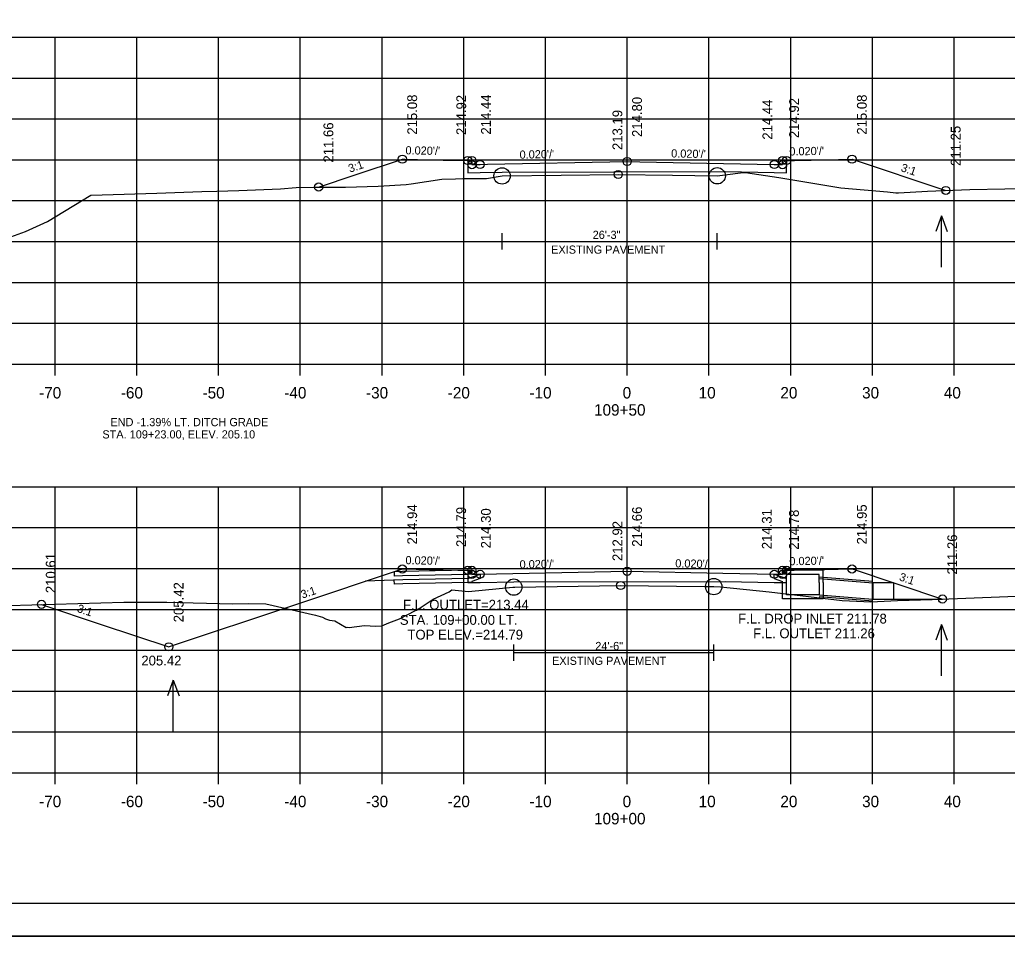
# Model space of a CAD drawing. Extents: x 1368968 to 1369915, y 377395 to 380381.
# Drawn here: x 1369063.8 to 1369184.6, y 379541.1 to 379653.2 of the extents above; entities that cross this region are included whole.
import ezdxf

# ---------------------------------------------------------------- set-up
doc = ezdxf.new("R2010")
doc.units = 0
for name, color, linetype in [('Default', 7, 'Continuous'), ('S_BORDER_NO_PLOT', 7, 'Continuous'), ('S_BREAKLINE_ANNOT', 7, 'Continuous'), ('S_BRIDGE', 7, 'Continuous'), ('S_BRIDGE_ANNOT', 7, 'Continuous'), ('S_CONTOUR_MAJOR', 7, 'Continuous'), ('S_CROSS_DRAIN', 7, 'Continuous'), ('S_CTL_TABLE', 7, 'Continuous'), ('S_CURB_ANNOT', 7, 'Continuous'), ('S_DITCHLINE_ANNOT', 7, 'Continuous'), ('S_DROP_INLET', 7, 'Continuous'), ('S_EXIST_ROW_ANNOT', 7, 'Continuous'), ('S_EXISTING_ALIGNMENT', 7, 'Continuous'), ('S_EXISTING_ALIGNMENT_ANNOT', 7, 'Continuous'), ('S_FENCE', 7, 'Continuous')]:
    doc.layers.add(name, color=color, linetype=linetype)

msp = doc.modelspace()

# ---------------------------------------------------------------- linework, layer by layer
at = {"layer": 'Default'}
for p, q in [((1369168.2, 379584.32), (1369168.2, 379582.32)), ((1369170.7, 379584.32), (1369168.2, 379584.32)), ((1369170.7, 379584.32), (1369170.7, 379582.32)), ((1369168.2, 379582.32), (1369176.7, 379582.32))]:
    msp.add_line(p, q, dxfattribs=at)
at = {"layer": 'S_BORDER_NO_PLOT'}
for points in [[(1369118.62, 379635.97), (1369118.63, 379634.46), (1369120.13, 379634.49), (1369122.82, 379634.54), (1369150.13, 379634.61), (1369156.13, 379634.49), (1369157.63, 379634.46), (1369157.64, 379635.97)], [(1369118.62, 379585.84), (1369118.63, 379584.33), (1369120.13, 379584.36), (1369124.25, 379584.44), (1369150.13, 379584.48), (1369156.13, 379584.36), (1369157.63, 379584.33), (1369157.64, 379585.84)]]:
    msp.add_lwpolyline(points, dxfattribs=at)
at = {"layer": 'S_BREAKLINE_ANNOT'}
for p, q in [((1368998.13, 379611.06), (1369278.13, 379611.06)), ((1369068.13, 379609.66), (1369068.13, 379611.06)), ((1369078.13, 379609.66), (1369078.13, 379611.06)), ((1369088.13, 379609.66), (1369088.13, 379611.06)), ((1369098.13, 379609.66), (1369098.13, 379611.06)), ((1369108.13, 379609.66), (1369108.13, 379611.06)), ((1369118.13, 379609.66), (1369118.13, 379611.06)), ((1369128.13, 379609.66), (1369128.13, 379611.06)), ((1369138.13, 379609.66), (1369138.13, 379611.06)), ((1369148.13, 379609.66), (1369148.13, 379611.06)), ((1369158.13, 379609.66), (1369158.13, 379611.06)), ((1369168.13, 379609.66), (1369168.13, 379611.06)), ((1369178.13, 379609.66), (1369178.13, 379611.06)), ((1368998.13, 379561.06), (1369278.13, 379561.06)), ((1369068.13, 379559.66), (1369068.13, 379561.06)), ((1369078.13, 379559.66), (1369078.13, 379561.06)), ((1369088.13, 379559.66), (1369088.13, 379561.06)), ((1369098.13, 379559.66), (1369098.13, 379561.06)), ((1369108.13, 379559.66), (1369108.13, 379561.06)), ((1369118.13, 379559.66), (1369118.13, 379561.06)), ((1369128.13, 379559.66), (1369128.13, 379561.06)), ((1369138.13, 379559.66), (1369138.13, 379561.06)), ((1369148.13, 379559.66), (1369148.13, 379561.06)), ((1369158.13, 379559.66), (1369158.13, 379561.06)), ((1369168.13, 379559.66), (1369168.13, 379561.06)), ((1369178.13, 379559.66), (1369178.13, 379561.06))]:
    msp.add_line(p, q, dxfattribs=at)
at = {"layer": 'S_BRIDGE_ANNOT'}
msp.add_line((1369296.31, 379545.06), (1368980.13, 379545.06), dxfattribs=at)
at = {"layer": 'S_CROSS_DRAIN'}
for p, q in [((1369122.82, 379626.08), (1369149.14, 379626.08)), ((1369124.25, 379575.78), (1369148.72, 379575.78))]:
    msp.add_line(p, q, dxfattribs=at)
at = {"layer": 'S_CTL_TABLE'}
for points in [[(1369062.7, 379626.63), (1369064.5, 379627.28), (1369067.18, 379628.52), (1369072.51, 379631.73), (1369073.87, 379631.79), (1369080.58, 379631.97), (1369086.1, 379632.18), (1369087.91, 379632.24), (1369090.59, 379632.31), (1369091.63, 379632.34), (1369095.7, 379632.52), (1369097.63, 379632.65), (1369099.93, 379632.72), (1369103.68, 379632.72), (1369107.67, 379632.83), (1369111.07, 379633.04), (1369111.69, 379633.13), (1369115.45, 379633.7), (1369117.11, 379633.72), (1369118, 379633.78), (1369118.81, 379633.77), (1369120.9, 379633.79), (1369122.82, 379634.08), (1369130.06, 379634.18), (1369137.03, 379634.26), (1369143.67, 379634.18), (1369149.14, 379634.1), (1369151.99, 379634.46), (1369152.6, 379634.51), (1369156.67, 379633.88), (1369164.27, 379632.61), (1369169.99, 379632.13), (1369171, 379632.03), (1369171.15, 379632.02), (1369171.32, 379632.02), (1369174.89, 379632.23), (1369180.04, 379632.41), (1369188.63, 379632.57)], [(1369062.46, 379581.55), (1369076.55, 379581.96), (1369081.81, 379581.95), (1369089.87, 379581.74), (1369091.78, 379581.78), (1369093.93, 379581.72), (1369100, 379580.37), (1369100.83, 379580.1), (1369101.21, 379579.91), (1369101.7, 379579.73), (1369102.35, 379579.67), (1369103.73, 379578.86), (1369103.88, 379578.87), (1369104.12, 379578.86), (1369106, 379579.1), (1369107.38, 379578.99), (1369108.11, 379579.04), (1369108.95, 379579.41), (1369110.26, 379579.89), (1369112.21, 379580.91), (1369112.36, 379580.97), (1369112.67, 379581.15), (1369114.38, 379582.32), (1369116.34, 379583.21), (1369116.69, 379583.47), (1369118.71, 379583.25), (1369124.15, 379583.76), (1369124.25, 379583.78), (1369124.39, 379583.78), (1369137.32, 379583.98), (1369147.57, 379583.87), (1369148.72, 379583.85), (1369149.55, 379583.82), (1369155.5, 379583.22), (1369164.44, 379582.13), (1369167.07, 379582.02), (1369167.95, 379581.99), (1369171.19, 379582.13), (1369175.45, 379582.27), (1369188.81, 379582.79)]]:
    msp.add_lwpolyline(points, dxfattribs=at)
at = {"layer": 'S_CURB_ANNOT'}
for points in [[(1369100.37, 379632.72), (1369104.86, 379634.21), (1369110.62, 379636.13), (1369110.94, 379636.13), (1369115.62, 379636.03), (1369115.72, 379636.03), (1369117.46, 379636), (1369118.62, 379635.97), (1369119.12, 379635.97), (1369119.13, 379635.47), (1369119.72, 379635.48), (1369120.13, 379635.49), (1369121.03, 379635.51), (1369138.13, 379635.85), (1369139.67, 379635.82), (1369149.93, 379635.62), (1369156.13, 379635.49), (1369156.59, 379635.48), (1369157.13, 379635.47), (1369157.14, 379635.97), (1369157.63, 379635.97), (1369157.64, 379635.97), (1369157.7, 379635.97), (1369158.6, 379635.99), (1369160.64, 379636.03), (1369165.64, 379636.13), (1369177.12, 379632.31)], [(1369066.47, 379581.67), (1369073.77, 379579.23), (1369082.04, 379576.48), (1369082.12, 379576.5), (1369097.32, 379581.57), (1369110.62, 379586), (1369115.62, 379585.9), (1369117.41, 379585.87), (1369118.62, 379585.84), (1369118.62, 379585.84), (1369119.12, 379585.84), (1369119.13, 379585.34), (1369119.73, 379585.35), (1369120.13, 379585.36), (1369138.13, 379585.72), (1369149.81, 379585.49), (1369156.1, 379585.36), (1369156.13, 379585.36), (1369156.59, 379585.35), (1369157.13, 379585.34), (1369157.14, 379585.84), (1369157.64, 379585.84), (1369158.55, 379585.86), (1369160.64, 379585.9), (1369160.64, 379585.9), (1369165.63, 379586), (1369165.64, 379586), (1369176.69, 379582.32), (1369176.7, 379582.32)]]:
    msp.add_lwpolyline(points, dxfattribs=at)
at = {"layer": 'S_DITCHLINE_ANNOT'}
for p, q in [((1368998.13, 379651.06), (1369278.13, 379651.06)), ((1369068.13, 379611.06), (1369068.13, 379651.06)), ((1369078.13, 379611.06), (1369078.13, 379651.06)), ((1369088.13, 379611.06), (1369088.13, 379651.06)), ((1369098.13, 379611.06), (1369098.13, 379651.06)), ((1369108.13, 379611.06), (1369108.13, 379651.06)), ((1369118.13, 379611.06), (1369118.13, 379651.06)), ((1369128.13, 379611.06), (1369128.13, 379651.06)), ((1369138.13, 379611.06), (1369138.13, 379651.06)), ((1369148.13, 379611.06), (1369148.13, 379651.06)), ((1369158.13, 379611.06), (1369158.13, 379651.06)), ((1369168.13, 379611.06), (1369168.13, 379651.06)), ((1369178.13, 379611.06), (1369178.13, 379651.06)), ((1368998.13, 379646.06), (1369278.13, 379646.06)), ((1368998.13, 379641.06), (1369278.13, 379641.06)), ((1368998.13, 379636.06), (1369278.13, 379636.06)), ((1368998.13, 379631.06), (1369278.13, 379631.06)), ((1368998.13, 379626.06), (1369278.13, 379626.06)), ((1368998.13, 379621.06), (1369278.13, 379621.06)), ((1368998.13, 379616.06), (1369278.13, 379616.06)), ((1368998.13, 379611.06), (1369278.13, 379611.06)), ((1368998.13, 379596.06), (1369278.13, 379596.06)), ((1369068.13, 379561.06), (1369068.13, 379596.06)), ((1369078.13, 379561.06), (1369078.13, 379596.06)), ((1369088.13, 379561.06), (1369088.13, 379596.06)), ((1369098.13, 379561.06), (1369098.13, 379596.06)), ((1369108.13, 379561.06), (1369108.13, 379596.06)), ((1369118.13, 379561.06), (1369118.13, 379596.06)), ((1369128.13, 379561.06), (1369128.13, 379596.06)), ((1369138.13, 379561.06), (1369138.13, 379596.06)), ((1369148.13, 379561.06), (1369148.13, 379596.06)), ((1369158.13, 379561.06), (1369158.13, 379596.06)), ((1369168.13, 379561.06), (1369168.13, 379596.06)), ((1369178.13, 379561.06), (1369178.13, 379596.06)), ((1368998.13, 379591.06), (1369278.13, 379591.06)), ((1368998.13, 379586.06), (1369278.13, 379586.06)), ((1368998.13, 379581.06), (1369278.13, 379581.06)), ((1368998.13, 379576.06), (1369278.13, 379576.06)), ((1368998.13, 379571.06), (1369278.13, 379571.06)), ((1368998.13, 379566.06), (1369278.13, 379566.06)), ((1368998.13, 379561.06), (1369278.13, 379561.06))]:
    msp.add_line(p, q, dxfattribs=at)
at = {"layer": 'S_DROP_INLET'}
for p, q in [((1369161.61, 379585.05), (1369168.2, 379584.53)), ((1369161.61, 379582.63), (1369168.2, 379582.11)), ((1368967.73, 379541.08), (1369301.07, 379541.08))]:
    msp.add_line(p, q, dxfattribs=at)
for points in [[(1368967.73, 379754.41), (1369301.07, 379754.41), (1369301.07, 379541.07), (1368967.73, 379541.07)], [(1369214.05, 379750.52), (1369214.05, 379740.64), (1369249.79, 379740.64), (1369249.79, 379737.72), (1369272.99, 379737.72), (1369272.99, 379713.38), (1369296.31, 379713.38), (1369296.31, 379545.06), (1368980.13, 379545.06), (1368980.13, 379750.52)]]:
    msp.add_lwpolyline(points, close=True, dxfattribs=at)
for centre, radius in [((1369110.62, 379636.13), 0.5), ((1369118.62, 379635.97), 0.5), ((1369119.12, 379635.97), 0.5), ((1369119.13, 379635.47), 0.5), ((1369120.13, 379635.49), 0.5), ((1369120.13, 379635.49), 0.5), ((1369138.13, 379635.85), 0.5), ((1369156.13, 379635.49), 0.5), ((1369156.13, 379635.49), 0.5), ((1369157.13, 379635.47), 0.5), ((1369157.14, 379635.97), 0.5), ((1369157.64, 379635.97), 0.5), ((1369165.64, 379636.13), 0.5), ((1369122.82, 379634.08), 1), ((1369137.03, 379634.26), 0.5), ((1369149.14, 379634.1), 1), ((1369100.37, 379632.72), 0.5), ((1369177.12, 379632.31), 0.5), ((1369110.62, 379586), 0.5), ((1369118.62, 379585.84), 0.5), ((1369119.12, 379585.84), 0.5), ((1369138.13, 379585.72), 0.5), ((1369157.14, 379585.84), 0.5), ((1369157.64, 379585.84), 0.5), ((1369165.64, 379586), 0.5), ((1369119.13, 379585.34), 0.5), ((1369120.13, 379585.36), 0.5), ((1369120.13, 379585.36), 0.5), ((1369156.13, 379585.36), 0.5), ((1369156.13, 379585.36), 0.5), ((1369157.13, 379585.34), 0.5), ((1369124.25, 379583.78), 1), ((1369137.32, 379583.98), 0.5), ((1369148.72, 379583.85), 1), ((1369176.7, 379582.32), 0.5), ((1369066.47, 379581.67), 0.5), ((1369082.04, 379576.48), 0.5)]:
    msp.add_circle(centre, radius, dxfattribs=at)
at = {"layer": 'S_EXIST_ROW_ANNOT'}
for p, q in [((1369122.82, 379625.08), (1369122.82, 379627.08)), ((1369149.14, 379625.08), (1369149.14, 379627.08)), ((1369110.64, 379585.68), (1369109.61, 379585.64)), ((1369109.61, 379585.64), (1369109.62, 379585.14)), ((1369110.65, 379585.18), (1369109.62, 379585.14)), ((1369118.63, 379585.84), (1369110.64, 379585.68)), ((1369118.64, 379585.34), (1369110.65, 379585.18)), ((1369156.11, 379585.36), (1369157.61, 379584.84)), ((1369157.28, 379585.67), (1369157.36, 379585.84)), ((1369157.28, 379585.67), (1369157.61, 379585.34)), ((1369162.11, 379585.84), (1369157.36, 379585.84)), ((1369161.61, 379585.34), (1369157.61, 379585.34)), ((1369161.61, 379584.34), (1369161.61, 379585.34)), ((1369162.11, 379584.34), (1369162.11, 379585.84)), ((1369110.66, 379584.68), (1369106.12, 379584.5)), ((1369109.64, 379584.14), (1369109.63, 379584.64)), ((1369110.67, 379584.18), (1369109.64, 379584.14)), ((1369118.65, 379584.84), (1369110.66, 379584.68)), ((1369118.66, 379584.34), (1369110.67, 379584.18)), ((1369156.11, 379584.83), (1369157.11, 379584.48)), ((1369157.11, 379584.34), (1369157.11, 379584.48)), ((1369157.61, 379584.34), (1369157.61, 379584.84)), ((1369161.61, 379584.84), (1369168.2, 379584.32)), ((1369161.61, 379582.84), (1369168.2, 379582.32)), ((1369124.25, 379574.78), (1369124.25, 379576.78)), ((1369148.72, 379574.78), (1369148.72, 379576.78))]:
    msp.add_line(p, q, dxfattribs=at)
for points in [[(1369118.63, 379585.84), (1369118.88, 379585.84), (1369118.97, 379585.68), (1369118.63, 379585.34)], [(1369118.63, 379584.84), (1369120.13, 379585.36), (1369120.13, 379584.83), (1369119.13, 379584.49), (1369119.13, 379584.34), (1369118.63, 379584.34)], [(1369156.11, 379584.83), (1369156.11, 379585.36)], [(1369162.11, 379584.34), (1369162.11, 379582.34), (1369159.61, 379582.34), (1369157.11, 379582.34), (1369157.11, 379584.34)], [(1369161.61, 379584.34), (1369161.61, 379582.84), (1369159.61, 379582.84), (1369157.61, 379582.84), (1369157.61, 379584.34)]]:
    msp.add_lwpolyline(points, dxfattribs=at)
at = {"layer": 'S_EXISTING_ALIGNMENT'}
for p, q in [((1369176.59, 379629.22), (1369175.89, 379627.29)), ((1369176.59, 379622.93), (1369176.59, 379629.22)), ((1369176.59, 379629.22), (1369177.29, 379627.29)), ((1369176.59, 379579.22), (1369175.89, 379577.3)), ((1369176.59, 379572.94), (1369176.59, 379579.22)), ((1369176.59, 379579.22), (1369177.29, 379577.3)), ((1369082.59, 379572.4), (1369081.89, 379570.48)), ((1369082.59, 379566.12), (1369082.59, 379572.4)), ((1369082.59, 379572.4), (1369083.29, 379570.48))]:
    msp.add_line(p, q, dxfattribs=at)
at = {"layer": 'S_EXISTING_ALIGNMENT_ANNOT'}
for p, q in [((1369138.13, 379634.25), (1369138.13, 379644.25)), ((1369138.13, 379583.97), (1369138.13, 379593.97))]:
    msp.add_line(p, q, dxfattribs=at)

# ---------------------------------------------------------------- texts
at = {"layer": 'S_BRIDGE'}
for s, p in [('-70', (1369066.17, 379606.86)), ('-60', (1369076.17, 379606.86)), ('-50', (1369086.17, 379606.86)), ('-40', (1369096.17, 379606.86)), ('-30', (1369106.17, 379606.86)), ('-20', (1369116.17, 379606.86)), ('-10', (1369126.17, 379606.86)), ('0', (1369137.57, 379606.86)), ('10', (1369146.87, 379606.86)), ('20', (1369156.87, 379606.86)), ('30', (1369166.87, 379606.86)), ('40', (1369176.87, 379606.86)), ('109+50', (1369134.07, 379604.76)), ('-70', (1369066.17, 379556.86)), ('-60', (1369076.17, 379556.86)), ('-50', (1369086.17, 379556.86)), ('-40', (1369096.17, 379556.86)), ('-30', (1369106.17, 379556.86)), ('-20', (1369116.17, 379556.86)), ('-10', (1369126.17, 379556.86)), ('0', (1369137.57, 379556.86)), ('10', (1369146.87, 379556.86)), ('20', (1369156.87, 379556.86)), ('30', (1369166.87, 379556.86)), ('40', (1369176.87, 379556.86)), ('109+00', (1369134.07, 379554.76))]:
    msp.add_text(s, height=1.4, dxfattribs=at).set_placement(p)
at = {"layer": 'S_CONTOUR_MAJOR'}
for s, height, p in [('END -1.39% LT. DITCH GRADE', 1, (1369074.89, 379603.47)), ('STA. 109+23.00, ELEV. 205.10', 1, (1369073.91, 379601.97)), ('205.42', 1.2, (1369078.68, 379574.2))]:
    msp.add_text(s, height=height, dxfattribs=at).set_placement(p)
at = {"layer": 'S_EXIST_ROW_ANNOT'}
for s, height, p in [('26\'-3"', 1, (1369133.9, 379626.38)), ('EXISTING PAVEMENT', 1, (1369128.82, 379624.57)), ('F.L. OUTLET=213.44', 1.2, (1369110.7, 379581.03)), ('STA. 109+00.00 LT.', 1.2, (1369110.31, 379579.17)), ('F.L. DROP INLET 211.78', 1.2, (1369151.7, 379579.33)), ('TOP ELEV.=214.79', 1.2, (1369111.24, 379577.37)), ('F.L. OUTLET 211.26', 1.2, (1369153.54, 379577.53)), ('24\'-6"', 1, (1369134.22, 379576.08)), ('EXISTING PAVEMENT', 1, (1369128.93, 379574.27))]:
    msp.add_text(s, height=height, dxfattribs=at).set_placement(p)
at = {"layer": 'S_EXISTING_ALIGNMENT_ANNOT'}
for s, p in [('215.08', (1369112.42, 379639.13)), ('214.92', (1369118.42, 379639.09)), ('214.44', (1369121.45, 379639.14)), ('214.80', (1369139.93, 379638.85)), ('214.44', (1369155.88, 379638.52)), ('214.92', (1369159.15, 379638.71)), ('215.08', (1369167.44, 379639.13)), ('213.19', (1369137.53, 379637.25)), ('211.66', (1369102.17, 379635.72)), ('211.25', (1369178.92, 379635.31)), ('214.94', (1369112.42, 379589)), ('214.79', (1369118.41, 379588.69)), ('214.30', (1369121.44, 379588.52)), ('214.66', (1369139.93, 379588.72)), ('214.95', (1369167.44, 379589)), ('214.31', (1369155.81, 379588.42)), ('214.78', (1369159.13, 379588.35)), ('212.92', (1369137.53, 379586.97)), ('211.26', (1369178.5, 379585.32)), ('210.61', (1369068.19, 379583.05)), ('205.42', (1369083.84, 379579.48))]:
    msp.add_text(s, height=1.2, rotation=90, dxfattribs=at).set_placement(p)
at = {"layer": 'S_FENCE'}
for s, rotation, p in [("0.020'/'", 358.8542, (1369110.99, 379636.73)), ("0.020'/'", 1.1458, (1369124.97, 379636.19)), ("0.020'/'", 358.8542, (1369143.5, 379636.35)), ("0.020'/'", 1.1458, (1369157.98, 379636.58)), ('3:1', 18.433, (1369104.2, 379634.48)), ('3:1', 341.568, (1369171.54, 379634.69)), ("0.020'/'", 358.8543, (1369110.99, 379586.59)), ("0.020'/'", 1.1458, (1369157.98, 379586.45)), ("0.020'/'", 1.1458, (1369124.97, 379586.06)), ("0.020'/'", 358.8542, (1369144, 379586.2)), ('3:1', 341.5666, (1369171.33, 379584.63)), ('3:1', 18.4335, (1369098.39, 379582.37)), ('3:1', 341.5681, (1369070.74, 379580.77))]:
    msp.add_text(s, height=1, rotation=rotation, dxfattribs=at).set_placement(p)

doc.saveas('drawing.dxf')
